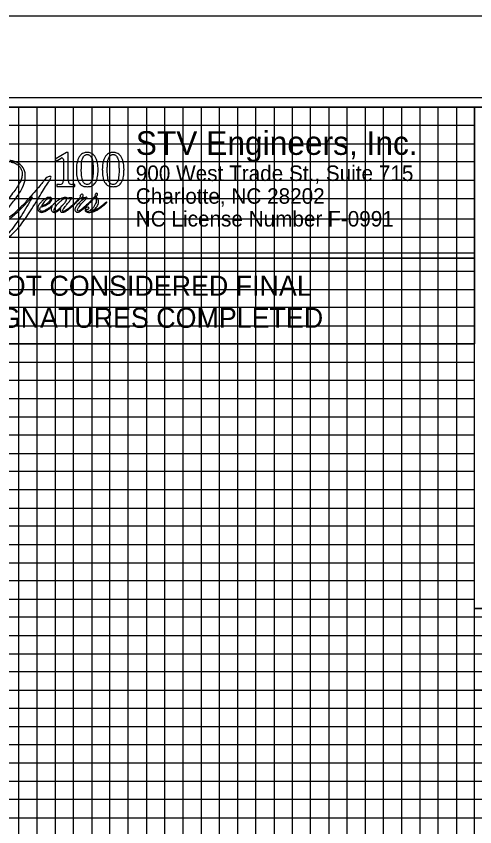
# Model space of a CAD drawing. Extents: x 3814791 to 3815465, y 1224203 to 1224643.
# Drawn here: x 3815327.8 to 3815378.1, y 1224554.2 to 1224643.2 of the extents above; entities that cross this region are included whole.
import ezdxf

# ---------------------------------------------------------------- set-up
doc = ezdxf.new("R2010")
doc.units = 0
for name, color, linetype in [('COGO Default Curve', 7, 'Continuous'), ('Exist Roads EOP', 7, 'Continuous'), ('Pattern 49', 7, 'Continuous'), ('Scratch_Level_1', 7, 'Continuous'), ('Sheet Data Field CELL', 7, 'Continuous'), ('Sheet Layout Plan Border', 7, 'Continuous'), ('UC Full Profile Sheet 34 CELL', 7, 'Continuous')]:
    doc.layers.add(name, color=color, linetype=linetype)

msp = doc.modelspace()

# ---------------------------------------------------------------- linework, layer by layer
at = {"layer": 'COGO Default Curve'}
for p, q in [((3815298.107, 1224616.652), (3815378.107, 1224616.652)), ((3815378.107, 1224616.652), (3815378.107, 1224607.252)), ((3815378.107, 1224607.252), (3815298.107, 1224607.252))]:
    msp.add_line(p, q, dxfattribs=at)
at = {"layer": 'Exist Roads EOP'}
for p, q in [((3814878.107, 1224633.207), (3815378.107, 1224633.207)), ((3815378.107, 1224623.187), (3815378.132, 1224633.207)), ((3815438.107, 1224561.207), (3814878.107, 1224561.207)), ((3814878.107, 1224559.207), (3815438.107, 1224559.207))]:
    msp.add_line(p, q, dxfattribs=at)
for points in [[(3815458.107, 1224633.207), (3814858.107, 1224633.207), (3814858.107, 1224213.207), (3815458.107, 1224213.207)], [(3814878.107, 1224633.207), (3814878.107, 1224223.207), (3815438.107, 1224223.207), (3815438.107, 1224578.187), (3815378.107, 1224578.187), (3815378.107, 1224633.207)]]:
    msp.add_lwpolyline(points, close=True, dxfattribs=at)
for points in [[(3815328.107, 1224223.207), (3815328.107, 1224633.207), (3815348.107, 1224633.207), (3815348.107, 1224223.207)], [(3815330.107, 1224223.207), (3815330.107, 1224633.207), (3815332.107, 1224633.207), (3815332.107, 1224223.207)], [(3815334.107, 1224223.207), (3815334.107, 1224633.207), (3815336.107, 1224633.207), (3815336.107, 1224223.207)], [(3815338.107, 1224223.207), (3815338.107, 1224633.207), (3815358.107, 1224633.207), (3815358.107, 1224223.207)], [(3815340.107, 1224223.207), (3815340.107, 1224633.207), (3815342.107, 1224633.207), (3815342.107, 1224223.207)], [(3815344.107, 1224223.207), (3815344.107, 1224633.207), (3815346.107, 1224633.207), (3815346.107, 1224223.207)], [(3815350.107, 1224223.207), (3815350.107, 1224633.207), (3815352.107, 1224633.207), (3815352.107, 1224223.207)], [(3815354.107, 1224223.207), (3815354.107, 1224633.207), (3815356.107, 1224633.207), (3815356.107, 1224223.207)], [(3815360.107, 1224223.207), (3815360.107, 1224633.207), (3815362.107, 1224633.207), (3815362.107, 1224223.207)], [(3815364.107, 1224223.207), (3815364.107, 1224633.207), (3815366.107, 1224633.207), (3815366.107, 1224223.207)], [(3815368.107, 1224223.207), (3815368.107, 1224633.207)], [(3815370.107, 1224223.207), (3815370.107, 1224633.207), (3815372.107, 1224633.207), (3815372.107, 1224223.207)], [(3815374.107, 1224223.207), (3815374.107, 1224633.207), (3815376.107, 1224633.207), (3815376.107, 1224223.207)], [(3815378.107, 1224223.207), (3815378.107, 1224633.207), (3815388.627, 1224633.207)], [(3815418.137, 1224623.252), (3815418.137, 1224578.187), (3815378.107, 1224578.187), (3815378.107, 1224633.207), (3815418.137, 1224633.207), (3815418.137, 1224633.147)], [(3815378.087, 1224631.207), (3814878.107, 1224631.207), (3814878.107, 1224629.207), (3815378.087, 1224629.207)], [(3815378.087, 1224627.207), (3814878.107, 1224627.207), (3814878.107, 1224625.207), (3815378.087, 1224625.207)], [(3815378.087, 1224603.207), (3814858.147, 1224603.207), (3814858.147, 1224623.187), (3815378.087, 1224623.187)], [(3815378.087, 1224620.907), (3814878.107, 1224620.907)], [(3815378.087, 1224618.907), (3814878.107, 1224618.907)], [(3815378.087, 1224617.207), (3814878.107, 1224617.207), (3814878.107, 1224615.207), (3815378.087, 1224615.207)], [(3814858.107, 1224613.207), (3815378.087, 1224613.207)], [(3815378.087, 1224611.207), (3814878.107, 1224611.207), (3814878.107, 1224609.207), (3815378.087, 1224609.207)], [(3815378.107, 1224607.207), (3814878.107, 1224607.207), (3814878.107, 1224605.207), (3815378.087, 1224605.207)], [(3815378.087, 1224601.207), (3814878.107, 1224601.207), (3814878.107, 1224599.207), (3815378.087, 1224599.207)], [(3815378.087, 1224597.207), (3814878.107, 1224597.207), (3814878.107, 1224595.207), (3815378.087, 1224595.207)], [(3815378.087, 1224593.207), (3814858.107, 1224593.207), (3814858.107, 1224573.187), (3815458.107, 1224573.187)], [(3815378.087, 1224591.207), (3814878.107, 1224591.207), (3814878.107, 1224589.207), (3815378.087, 1224589.207)], [(3815378.087, 1224587.207), (3814878.107, 1224587.207), (3814878.107, 1224585.207), (3815378.087, 1224585.207)], [(3815458.107, 1224563.207), (3814858.107, 1224563.207), (3814858.107, 1224583.207), (3815378.087, 1224583.207)], [(3815378.087, 1224581.207), (3814878.107, 1224581.207), (3814878.107, 1224579.207), (3815378.087, 1224579.207)], [(3815438.107, 1224577.207), (3814878.107, 1224577.207), (3814878.107, 1224577.207), (3814878.107, 1224569.207), (3815438.107, 1224569.207)], [(3814878.107, 1224575.207), (3815438.107, 1224575.207)], [(3815438.107, 1224571.207), (3814878.107, 1224571.207)], [(3815438.107, 1224567.207), (3814878.107, 1224567.207), (3814878.107, 1224565.207), (3815438.107, 1224565.207)], [(3815438.107, 1224557.207), (3814878.107, 1224557.207), (3814878.107, 1224555.207), (3815438.107, 1224555.207)]]:
    msp.add_lwpolyline(points, dxfattribs=at)
at = {"layer": 'Pattern 49'}
msp.add_lwpolyline([(3815463.107, 1224634.227), (3814796.507, 1224634.227), (3814796.507, 1224212.187), (3815463.107, 1224212.187)], close=True, dxfattribs=at)
at = {"layer": 'Scratch_Level_1'}
msp.add_lwpolyline([(3815464.907, 1224643.207), (3814791.307, 1224643.207), (3814791.307, 1224203.207), (3815464.907, 1224203.207)], close=True, dxfattribs=at)
at = {"layer": 'Sheet Data Field CELL'}
msp.add_lwpolyline([(3815378.107, 1224578.187), (3815458.107, 1224578.187), (3815458.107, 1224569.207), (3815378.107, 1224569.207)], close=True, dxfattribs=at)
at = {"layer": 'Sheet Layout Plan Border'}
for p, q in [((3815333.337, 1224628.261), (3815332.095, 1224627.499)), ((3815332.222, 1224627.301), (3815332.737, 1224627.617)), ((3815333.51, 1224628.261), (3815333.337, 1224628.261)), ((3815333.51, 1224625.153), (3815333.51, 1224628.261)), ((3815332.095, 1224627.499), (3815332.222, 1224627.301)), ((3815333.008, 1224627.465), (3815333.008, 1224625.153)), ((3815332.581, 1224624.726), (3815332.261, 1224624.726)), ((3815332.261, 1224624.726), (3815332.261, 1224624.517)), ((3815332.261, 1224624.517), (3815334.258, 1224624.517)), ((3815334.258, 1224624.726), (3815333.938, 1224624.726)), ((3815334.258, 1224624.517), (3815334.258, 1224624.726)), ((3815335.613, 1224624.718), (3815335.61, 1224624.718)), ((3815335.611, 1224624.489), (3815335.612, 1224624.489)), ((3815338.456, 1224624.718), (3815338.454, 1224624.718)), ((3815338.455, 1224624.489), (3815338.455, 1224624.489))]:
    msp.add_line(p, q, dxfattribs=at)
msp.add_lwpolyline([(3815298.107, 1224633.207), (3815378.107, 1224633.207), (3815378.107, 1224616.652), (3815298.107, 1224616.652)], close=True, dxfattribs=at)
for centre, radius, start, end in [((3815332.83, 1224627.465), 0.178, 360, 121.52681), ((3815332.581, 1224625.153), 0.428, 270, 0), ((3815333.938, 1224625.153), 0.428, 180, 270)]:
    msp.add_arc(centre, radius, start, end, dxfattribs=at)
for points, degree in [([(3815335.611, 1224628.261), (3815335.58, 1224628.26), (3815335.478, 1224628.257), (3815335.31, 1224628.228), (3815335.097, 1224628.14), (3815334.88, 1224627.971), (3815334.681, 1224627.703), (3815334.561, 1224627.388), (3815334.47, 1224627.04), (3815334.43, 1224626.713), (3815334.423, 1224626.482), (3815334.421, 1224626.389)], 3), ([(3815334.964, 1224626.389), (3815334.968, 1224626.538), (3815334.977, 1224626.832), (3815334.991, 1224627.239), (3815335.078, 1224627.566), (3815335.193, 1224627.785), (3815335.31, 1224627.917), (3815335.425, 1224627.992), (3815335.513, 1224628.02), (3815335.575, 1224628.024), (3815335.611, 1224628.027)], 3), ([(3815336.802, 1224626.389), (3815336.799, 1224626.482), (3815336.793, 1224626.713), (3815336.753, 1224627.04), (3815336.662, 1224627.388), (3815336.541, 1224627.703), (3815336.342, 1224627.971), (3815336.126, 1224628.14), (3815335.913, 1224628.228), (3815335.745, 1224628.257), (3815335.643, 1224628.26), (3815335.611, 1224628.261)], 3), ([(3815335.611, 1224628.027), (3815335.648, 1224628.024), (3815335.71, 1224628.02), (3815335.798, 1224627.992), (3815335.913, 1224627.917), (3815336.03, 1224627.785), (3815336.145, 1224627.566), (3815336.232, 1224627.239), (3815336.246, 1224626.832), (3815336.254, 1224626.538), (3815336.259, 1224626.389)], 3), ([(3815338.455, 1224628.261), (3815338.424, 1224628.26), (3815338.321, 1224628.257), (3815338.154, 1224628.228), (3815337.94, 1224628.14), (3815337.724, 1224627.971), (3815337.525, 1224627.703), (3815337.405, 1224627.388), (3815337.314, 1224627.04), (3815337.274, 1224626.713), (3815337.267, 1224626.482), (3815337.265, 1224626.389)], 3), ([(3815337.808, 1224626.389), (3815337.812, 1224626.538), (3815337.821, 1224626.832), (3815337.835, 1224627.239), (3815337.922, 1224627.566), (3815338.036, 1224627.785), (3815338.153, 1224627.917), (3815338.269, 1224627.992), (3815338.357, 1224628.02), (3815338.419, 1224628.024), (3815338.455, 1224628.027)], 3), ([(3815339.646, 1224626.389), (3815339.643, 1224626.482), (3815339.636, 1224626.713), (3815339.597, 1224627.04), (3815339.505, 1224627.388), (3815339.385, 1224627.703), (3815339.186, 1224627.971), (3815338.97, 1224628.14), (3815338.756, 1224628.228), (3815338.589, 1224628.257), (3815338.486, 1224628.26), (3815338.455, 1224628.261)], 3), ([(3815338.455, 1224628.027), (3815338.491, 1224628.024), (3815338.553, 1224628.02), (3815338.641, 1224627.992), (3815338.757, 1224627.917), (3815338.874, 1224627.785), (3815338.989, 1224627.566), (3815339.075, 1224627.239), (3815339.09, 1224626.832), (3815339.098, 1224626.538), (3815339.102, 1224626.389)], 3), ([(3815329.579, 1224623.37), (3815329.48, 1224623.182), (3815329.145, 1224622.541), (3815328.559, 1224621.583), (3815327.905, 1224620.564), (3815327.301, 1224619.72), (3815326.755, 1224619.129), (3815326.278, 1224618.692), (3815325.912, 1224618.471), (3815325.578, 1224618.312), (3815325.273, 1224618.284), (3815325.005, 1224618.326), (3815324.819, 1224618.475), (3815324.729, 1224618.652), (3815324.739, 1224618.8), (3815324.823, 1224618.892), (3815324.952, 1224618.897), (3815325.113, 1224618.904), (3815325.316, 1224618.974), (3815325.376, 1224619.217), (3815325.208, 1224619.41), (3815324.944, 1224619.393), (3815324.741, 1224619.217), (3815324.57, 1224618.983), (3815324.588, 1224618.694), (3815324.672, 1224618.439), (3815324.863, 1224618.251), (3815325.148, 1224618.157), (3815325.447, 1224618.169), (3815325.782, 1224618.232), (3815326.176, 1224618.393), (3815326.609, 1224618.663), (3815327.118, 1224619.03), (3815327.702, 1224619.583), (3815328.276, 1224620.224), (3815328.842, 1224620.996), (3815329.371, 1224621.797), (3815330.015, 1224622.822), (3815330.587, 1224623.772), (3815331.072, 1224624.563), (3815331.375, 1224625.002), (3815331.546, 1224625.309), (3815331.648, 1224625.457), (3815331.669, 1224625.635), (3815331.494, 1224625.613), (3815331.348, 1224625.603), (3815331.179, 1224625.505), (3815330.995, 1224625.331), (3815330.752, 1224624.985), (3815330.309, 1224624.456), (3815329.642, 1224623.687), (3815328.836, 1224622.757), (3815327.977, 1224621.898), (3815327.33, 1224621.296), (3815326.897, 1224621.026), (3815326.704, 1224620.914), (3815326.492, 1224620.904), (3815326.428, 1224621.1), (3815326.477, 1224621.314), (3815326.661, 1224621.749), (3815326.984, 1224622.165), (3815327.421, 1224622.729), (3815327.888, 1224623.348), (3815328.443, 1224624.171), (3815328.82, 1224625.107), (3815328.854, 1224626.058), (3815328.487, 1224626.765), (3815327.968, 1224627.164), (3815327.513, 1224627.304), (3815327.23, 1224627.348), (3815327.124, 1224627.359)], 3), ([(3815327.277, 1224627.183), (3815327.281, 1224627.182), (3815327.347, 1224627.169), (3815327.47, 1224627.146), (3815327.702, 1224627.074), (3815327.938, 1224626.939), (3815328.175, 1224626.739), (3815328.324, 1224626.502), (3815328.443, 1224626.242), (3815328.481, 1224625.926), (3815328.461, 1224625.507), (3815328.279, 1224625.035), (3815327.959, 1224624.515), (3815327.58, 1224623.964), (3815327.008, 1224623.21), (3815326.426, 1224622.443), (3815326.116, 1224621.654), (3815326.097, 1224621.181), (3815326.2, 1224620.905), (3815326.385, 1224620.765), (3815326.559, 1224620.758), (3815326.796, 1224620.797), (3815327.062, 1224620.953), (3815327.382, 1224621.175), (3815327.809, 1224621.568), (3815328.345, 1224622.056), (3815328.964, 1224622.718), (3815329.362, 1224623.14), (3815329.579, 1224623.37)], 3), ([(3815334.421, 1224626.389), (3815334.423, 1224626.313), (3815334.43, 1224626.114), (3815334.434, 1224625.794), (3815334.504, 1224625.445), (3815334.6, 1224625.113), (3815334.756, 1224624.846), (3815334.947, 1224624.65), (3815335.225, 1224624.499), (3815335.458, 1224624.493), (3815335.611, 1224624.489)], 3), ([(3815335.61, 1224624.718), (3815335.559, 1224624.722), (3815335.437, 1224624.732), (3815335.272, 1224624.854), (3815335.128, 1224625.072), (3815335.027, 1224625.369), (3815334.993, 1224625.723), (3815334.958, 1224626.064), (3815334.962, 1224626.287), (3815334.964, 1224626.389)], 3), ([(3815335.612, 1224624.489), (3815335.765, 1224624.493), (3815335.998, 1224624.499), (3815336.276, 1224624.65), (3815336.467, 1224624.846), (3815336.622, 1224625.113), (3815336.718, 1224625.445), (3815336.789, 1224625.794), (3815336.793, 1224626.114), (3815336.799, 1224626.313), (3815336.802, 1224626.389)], 3), ([(3815336.259, 1224626.389), (3815336.261, 1224626.287), (3815336.265, 1224626.064), (3815336.23, 1224625.723), (3815336.196, 1224625.369), (3815336.094, 1224625.072), (3815335.951, 1224624.854), (3815335.786, 1224624.732), (3815335.664, 1224624.722), (3815335.613, 1224624.718)], 3), ([(3815337.265, 1224626.389), (3815337.267, 1224626.313), (3815337.274, 1224626.114), (3815337.277, 1224625.794), (3815337.348, 1224625.445), (3815337.444, 1224625.113), (3815337.6, 1224624.846), (3815337.791, 1224624.65), (3815338.069, 1224624.499), (3815338.301, 1224624.493), (3815338.455, 1224624.489)], 3), ([(3815338.454, 1224624.718), (3815338.403, 1224624.722), (3815338.281, 1224624.732), (3815338.115, 1224624.854), (3815337.972, 1224625.072), (3815337.87, 1224625.369), (3815337.837, 1224625.723), (3815337.802, 1224626.064), (3815337.806, 1224626.287), (3815337.808, 1224626.389)], 3), ([(3815338.455, 1224624.489), (3815338.609, 1224624.493), (3815338.842, 1224624.499), (3815339.119, 1224624.65), (3815339.31, 1224624.846), (3815339.466, 1224625.113), (3815339.562, 1224625.445), (3815339.633, 1224625.794), (3815339.636, 1224626.114), (3815339.643, 1224626.313), (3815339.646, 1224626.389)], 3), ([(3815339.102, 1224626.389), (3815339.104, 1224626.287), (3815339.108, 1224626.064), (3815339.074, 1224625.723), (3815339.04, 1224625.369), (3815338.938, 1224625.072), (3815338.795, 1224624.854), (3815338.629, 1224624.732), (3815338.508, 1224624.722), (3815338.456, 1224624.718)], 3), ([(3815333.471, 1224623.121), (3815333.462, 1224623.211), (3815333.416, 1224623.286), (3815333.222, 1224623.302), (3815332.959, 1224623.285), (3815332.68, 1224623.157), (3815332.445, 1224623.018), (3815332.199, 1224622.849), (3815331.979, 1224622.631), (3815331.756, 1224622.4), (3815331.433, 1224622.156), (3815331.315, 1224622.078), (3815331.115, 1224621.94), (3815330.901, 1224621.853), (3815330.721, 1224621.773), (3815330.575, 1224621.785), (3815330.472, 1224621.839), (3815330.405, 1224621.944), (3815330.406, 1224622.082), (3815330.469, 1224622.178), (3815330.511, 1224622.273), (3815330.641, 1224622.29), (3815330.819, 1224622.35), (3815331.038, 1224622.423), (3815331.266, 1224622.564), (3815331.503, 1224622.714), (3815331.684, 1224622.926), (3815331.765, 1224623.171), (3815331.633, 1224623.326), (3815331.478, 1224623.322), (3815331.273, 1224623.305), (3815331.014, 1224623.178), (3815330.707, 1224622.985), (3815330.449, 1224622.69), (3815330.232, 1224622.425), (3815330.179, 1224622.159), (3815330.193, 1224621.979), (3815330.269, 1224621.815), (3815330.4, 1224621.722), (3815330.552, 1224621.666), (3815330.735, 1224621.672), (3815330.989, 1224621.761), (3815331.254, 1224621.924), (3815331.535, 1224622.108), (3815331.685, 1224622.249), (3815331.757, 1224622.317)], 3), ([(3815330.585, 1224622.374), (3815330.635, 1224622.45), (3815330.728, 1224622.589), (3815330.903, 1224622.828), (3815331.081, 1224623.025), (3815331.277, 1224623.157), (3815331.387, 1224623.234), (3815331.488, 1224623.253), (3815331.561, 1224623.229), (3815331.607, 1224623.146), (3815331.553, 1224623.011), (3815331.452, 1224622.87), (3815331.293, 1224622.715), (3815331.099, 1224622.577), (3815330.905, 1224622.498), (3815330.734, 1224622.423), (3815330.642, 1224622.393), (3815330.585, 1224622.374)], 3), ([(3815332.66, 1224622.188), (3815332.586, 1224622.125), (3815332.415, 1224621.98), (3815332.216, 1224621.801), (3815332.024, 1224621.747), (3815331.916, 1224621.799), (3815331.92, 1224621.947), (3815332.013, 1224622.158), (3815332.279, 1224622.491), (3815332.578, 1224622.804), (3815332.849, 1224623.04), (3815333.009, 1224623.139), (3815333.144, 1224623.182), (3815333.269, 1224623.196), (3815333.406, 1224623.068), (3815333.238, 1224622.821), (3815333.052, 1224622.594), (3815332.842, 1224622.367), (3815332.708, 1224622.235), (3815332.66, 1224622.188)], 3), ([(3815332.691, 1224622.087), (3815332.681, 1224622.051), (3815332.657, 1224621.964), (3815332.645, 1224621.822), (3815332.737, 1224621.675), (3815332.915, 1224621.667), (3815333.167, 1224621.7), (3815333.461, 1224621.922), (3815333.803, 1224622.16), (3815334.074, 1224622.427), (3815334.324, 1224622.658), (3815334.571, 1224622.916), (3815334.749, 1224623.108), (3815334.848, 1224623.215)], 3), ([(3815336.019, 1224621.775), (3815336.06, 1224621.797), (3815336.194, 1224621.867), (3815336.403, 1224622.012), (3815336.61, 1224622.199), (3815336.765, 1224622.425), (3815336.845, 1224622.676), (3815336.854, 1224622.946), (3815336.771, 1224623.146), (3815336.671, 1224623.263), (3815336.635, 1224623.342), (3815336.592, 1224623.387), (3815336.608, 1224623.448), (3815336.675, 1224623.472), (3815336.718, 1224623.556), (3815336.742, 1224623.646), (3815336.707, 1224623.76), (3815336.587, 1224623.77), (3815336.516, 1224623.686), (3815336.464, 1224623.581), (3815336.491, 1224623.428), (3815336.326, 1224623.304), (3815336.156, 1224623.103), (3815335.85, 1224622.807), (3815335.545, 1224622.496), (3815335.265, 1224622.259), (3815335.104, 1224622.103), (3815334.969, 1224621.986), (3815334.827, 1224621.894), (3815334.717, 1224621.823), (3815334.576, 1224621.801), (3815334.538, 1224621.936), (3815334.57, 1224622.041), (3815334.653, 1224622.193), (3815334.776, 1224622.379), (3815334.944, 1224622.599), (3815335.114, 1224622.78), (3815335.287, 1224622.949), (3815335.431, 1224623.106), (3815335.557, 1224623.191), (3815335.612, 1224623.271), (3815335.543, 1224623.356), (3815335.429, 1224623.3), (3815335.306, 1224623.256), (3815335.194, 1224623.267), (3815334.981, 1224623.267), (3815335.043, 1224623.326), (3815335.081, 1224623.367), (3815335.168, 1224623.438), (3815335.167, 1224623.582), (3815335.069, 1224623.677), (3815334.948, 1224623.654), (3815334.869, 1224623.563), (3815334.822, 1224623.454), (3815334.84, 1224623.365), (3815334.79, 1224623.235), (3815334.627, 1224623.094), (3815334.384, 1224622.842), (3815334.095, 1224622.556), (3815333.733, 1224622.245), (3815333.432, 1224622), (3815333.187, 1224621.848), (3815333.062, 1224621.782), (3815332.967, 1224621.774), (3815332.91, 1224621.814), (3815332.906, 1224621.884), (3815332.941, 1224621.953), (3815333.026, 1224622.096), (3815333.175, 1224622.304), (3815333.454, 1224622.631), (3815333.715, 1224622.953), (3815333.894, 1224623.192), (3815333.949, 1224623.266)], 3), ([(3815333.594, 1224623.266), (3815333.553, 1224623.217), (3815333.512, 1224623.169), (3815333.471, 1224623.121)], 2), ([(3815333.949, 1224623.266), (3815333.831, 1224623.266), (3815333.712, 1224623.266), (3815333.594, 1224623.266)], 2), ([(3815335.217, 1224623.141), (3815335.128, 1224623.075), (3815334.947, 1224622.94), (3815334.738, 1224622.72), (3815334.549, 1224622.526), (3815334.41, 1224622.365), (3815334.314, 1224622.196), (3815334.258, 1224622.024), (3815334.258, 1224621.823), (3815334.43, 1224621.678), (3815334.638, 1224621.699), (3815334.843, 1224621.78), (3815335.074, 1224621.963), (3815335.378, 1224622.208), (3815335.855, 1224622.693), (3815336.23, 1224623.074), (3815336.49, 1224623.339)], 3), ([(3815334.848, 1224623.215), (3815334.883, 1224623.195), (3815334.96, 1224623.15), (3815335.091, 1224623.139), (3815335.179, 1224623.14), (3815335.217, 1224623.141)], 3), ([(3815336.49, 1224623.339), (3815336.515, 1224623.313), (3815336.589, 1224623.236), (3815336.602, 1224623.025), (3815336.595, 1224622.777), (3815336.466, 1224622.486), (3815336.298, 1224622.192), (3815336.08, 1224621.959), (3815335.894, 1224621.821), (3815335.741, 1224621.76), (3815335.605, 1224621.765), (3815335.519, 1224621.825), (3815335.476, 1224621.9), (3815335.505, 1224621.977), (3815335.561, 1224622.028), (3815335.635, 1224622.021), (3815335.719, 1224622.007), (3815335.793, 1224622.075), (3815335.826, 1224622.172), (3815335.723, 1224622.253), (3815335.579, 1224622.262), (3815335.451, 1224622.156), (3815335.384, 1224622.019), (3815335.374, 1224621.852), (3815335.498, 1224621.708), (3815335.74, 1224621.666), (3815336.033, 1224621.658), (3815336.353, 1224621.762), (3815336.686, 1224621.906), (3815337.005, 1224622.121), (3815337.357, 1224622.367), (3815337.59, 1224622.59), (3815337.754, 1224622.721), (3815337.766, 1224622.817), (3815337.689, 1224622.807), (3815337.602, 1224622.72), (3815337.461, 1224622.582), (3815337.211, 1224622.385), (3815336.951, 1224622.182), (3815336.663, 1224622.006), (3815336.412, 1224621.881), (3815336.201, 1224621.776), (3815336.067, 1224621.775), (3815336.019, 1224621.775)], 3), ([(3815331.757, 1224622.317), (3815331.731, 1224622.268), (3815331.687, 1224622.181), (3815331.656, 1224622.025), (3815331.678, 1224621.855), (3815331.8, 1224621.719), (3815331.968, 1224621.659), (3815332.141, 1224621.672), (3815332.308, 1224621.762), (3815332.446, 1224621.868), (3815332.574, 1224621.983), (3815332.651, 1224622.052), (3815332.691, 1224622.087)], 3)]:
    msp.add_open_spline(points, degree=degree, dxfattribs=at)
at = {"layer": 'UC Full Profile Sheet 34 CELL'}
for points in [[(3815298.107, 1224633.207), (3815378.107, 1224633.207), (3815378.107, 1224607.252), (3815333.021, 1224607.252), (3815318.649, 1224607.252), (3815298.107, 1224607.252)], [(3815378.107, 1224578.187), (3815458.107, 1224578.187), (3815458.107, 1224569.207), (3815416.023, 1224569.207), (3815402.086, 1224569.207), (3815378.107, 1224569.207)]]:
    msp.add_lwpolyline(points, close=True, dxfattribs=at)

# ---------------------------------------------------------------- texts
at = {"layer": 'COGO Default Curve'}
for s, p in [('DOCUMENT NOT CONSIDERED FINAL', (3815306.627, 1224612.514)), ('UNLESS ALL SIGNATURES COMPLETED', (3815304.599, 1224608.994))]:
    msp.add_text(s, height=2.2, rotation=360, dxfattribs=at).set_placement(p)
at = {"layer": 'Sheet Layout Plan Border'}
for s, height, p in [('STV Engineers, Inc.', 2.6, (3815340.936, 1224627.982)), ('900 West Trade St., Suite 715', 1.7, (3815340.936, 1224625.116)), ('Charlotte, NC 28202', 1.7, (3815340.936, 1224622.616)), ('NC License Number F-0991', 1.7, (3815340.936, 1224620.116))]:
    msp.add_text(s, height=height, rotation=360, dxfattribs=at).set_placement(p)

doc.saveas('drawing.dxf')
